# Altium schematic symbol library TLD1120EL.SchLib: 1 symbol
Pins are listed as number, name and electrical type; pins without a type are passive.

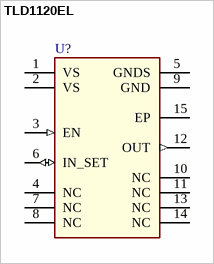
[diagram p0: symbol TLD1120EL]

## TLD1120EL
designator U?  (value not drawn)
Basic LED Driver, 1 Channel High Side Current Source; Manufacturer: Infineon Technologies
footprint SOP65P600X170-15N
pins: 1 VS (power) "Supply Voltage", 2 VS (power) "Supply Voltage", 3 EN (in) "Enable pin", 4 NC "Not Connected", 5 GNDS (power), 6 IN_SET (io) "Input / SET pin", 7 NC "Not Connected", 8 NC "Not Connected", 9 GND (power) "Ground", 10 NC "Not Connected", 11 NC "Not Connected", 12 OUT (out) "Output", 13 NC "Not Connected", 14 NC "Not Connected", 15 EP (power) "Exposed Pad"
